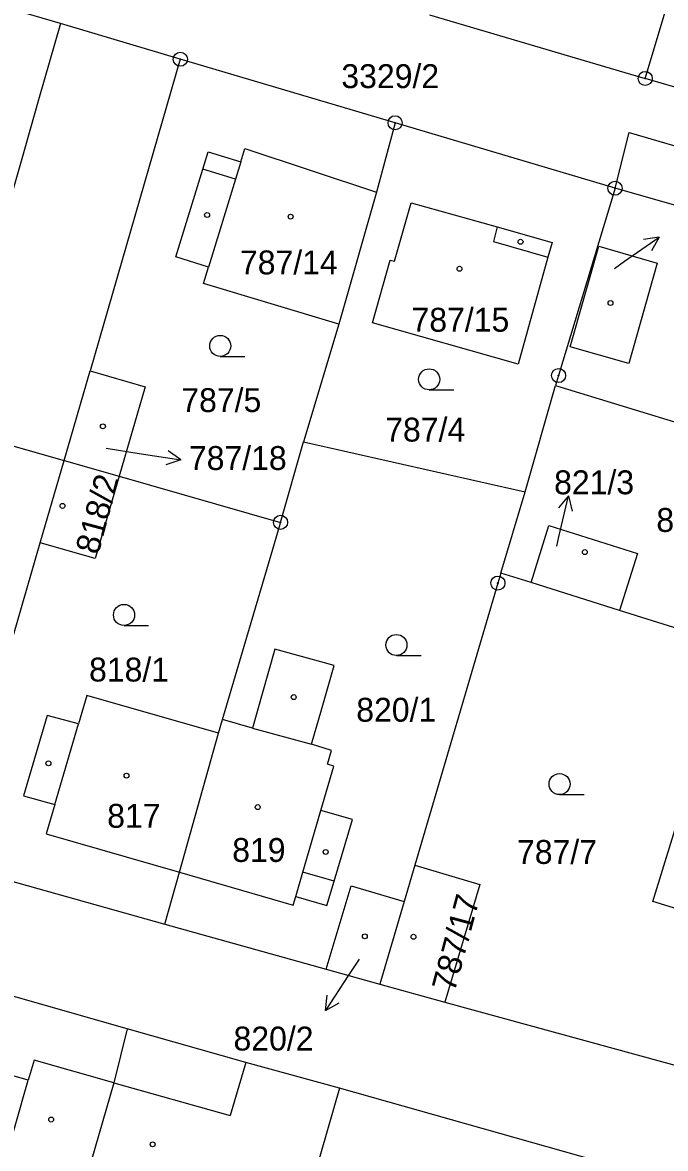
# Model space of a CAD drawing. Extents: x -733394 to -722299, y -1082822 to -1075049.
# Drawn here: x -727949 to -727903.3, y -1079541.3 to -1079461.1 of the extents above; entities that cross this region are included whole.
import ezdxf

# ---------------------------------------------------------------- set-up
doc = ezdxf.new("R2010")
doc.units = 0
for name, color, linetype in [('Hranice parcel', 7, 'Continuous'), ('Parcelní čísla', 7, 'Continuous'), ('Pop  PČ popisy', 7, 'Continuous'), ('Vnitřní kresba', 7, 'Continuous'), ('Značky bodu BP', 7, 'Continuous'), ('Značky budov', 7, 'Continuous'), ('Značky kultur', 7, 'Continuous')]:
    doc.layers.add(name, color=color, linetype=linetype)

msp = doc.modelspace()

# ---------------------------------------------------------------- linework, layer by layer
at = {"layer": 'Hranice parcel'}
for p, q in [((-727904.76, -1079465.11), (-727900.16, -1079449.75)), ((-727946.35, -1079461.21), (-727963.12, -1079456.31)), ((-727920.1, -1079460.58), (-727904.76, -1079465.11)), ((-727937.82, -1079463.75), (-727946.35, -1079461.21)), ((-727937.82, -1079463.75), (-727944.24, -1079485.92)), ((-727922.55, -1079468.27), (-727937.82, -1079463.75)), ((-727900.39, -1079466.39), (-727904.76, -1079465.11)), ((-727922.55, -1079468.27), (-727923.86, -1079473.2)), ((-727906.91, -1079472.93), (-727922.55, -1079468.27)), ((-727923.86, -1079473.2), (-727926.55, -1079482.61)), ((-727926.55, -1079482.61), (-727929.05, -1079490.99)), ((-727946.09, -1079492.3), (-727944.24, -1079485.92)), ((-727913.31, -1079494.53), (-727911.13, -1079486.97)), ((-727911.13, -1079486.97), (-727894.02, -1079492.21)), ((-727961.46, -1079487.91), (-727946.09, -1079492.3)), ((-727930.69, -1079496.71), (-727929.05, -1079490.99)), ((-727929.05, -1079490.99), (-727913.31, -1079494.53)), ((-727947.78, -1079498.16), (-727946.09, -1079492.3)), ((-727946.09, -1079492.3), (-727942.18, -1079493.42)), ((-727942.18, -1079493.42), (-727930.69, -1079496.71)), ((-727915.03, -1079500.32), (-727913.31, -1079494.53)), ((-727950.3, -1079506.88), (-727947.78, -1079498.16)), ((-727912.88, -1079501), (-727915.03, -1079500.32)), ((-727906.58, -1079502.98), (-727912.88, -1079501)), ((-727884.67, -1079509.87), (-727906.58, -1079502.98)), ((-727935.1, -1079511.72), (-727934.82, -1079510.75)), ((-727937.89, -1079521.62), (-727935.1, -1079511.72)), ((-727954.37, -1079520.98), (-727938.93, -1079525.32)), ((-727921.14, -1079521.12), (-727921.91, -1079523.69)), ((-727938.93, -1079525.32), (-727937.89, -1079521.62)), ((-727921.91, -1079523.69), (-727923.63, -1079529.59)), ((-727938.93, -1079525.32), (-727927.45, -1079528.52)), ((-727941.59, -1079532.77), (-727956.81, -1079528.43)), ((-727927.45, -1079528.52), (-727923.63, -1079529.59)), ((-727923.63, -1079529.59), (-727919, -1079530.86)), ((-727941.59, -1079532.77), (-727942.56, -1079536.6)), ((-727942.56, -1079536.6), (-727945.32, -1079546.14)), ((-727926.5, -1079536.99), (-727928.68, -1079544.56)), ((-727895.83, -1079545.64), (-727926.5, -1079536.99))]:
    msp.add_line(p, q, dxfattribs=at)
for points in [[(-727946.35, -1079461.21), (-727947.9, -1079466.63), (-727949.1, -1079470.83), (-727950.81, -1079476.82), (-727951.24, -1079478.31), (-727968.06, -1079473.53), (-727963.12, -1079456.31)], [(-727906.91, -1079472.93), (-727905.91, -1079468.96), (-727874.74, -1079478.07)], [(-727926.55, -1079482.61), (-727936.17, -1079479.7), (-727935.81, -1079478.54), (-727938.15, -1079477.82), (-727936.23, -1079471.57), (-727935.85, -1079470.33), (-727933.51, -1079471.04), (-727933.24, -1079470.11), (-727923.86, -1079473.2)], [(-727906.91, -1079472.93), (-727910.92, -1079486.26), (-727911.13, -1079486.97)], [(-727876.2, -1079482.76), (-727877.72, -1079481.28), (-727879.94, -1079480.64), (-727906.91, -1079472.93)], [(-727911.38, -1079476.8), (-727911.68, -1079477.84), (-727913.8, -1079485.44), (-727924.16, -1079482.52), (-727922.9, -1079478.05), (-727922.59, -1079478.13), (-727921.4, -1079473.97), (-727915.28, -1079475.67), (-727911.38, -1079476.8)], [(-727905.93, -1079485.41), (-727910.1, -1079484.21), (-727908.05, -1079477.06), (-727903.91, -1079478.25), (-727905.93, -1079485.41)], [(-727944.24, -1079485.92), (-727940.31, -1079487.06), (-727942.18, -1079493.42)], [(-727942.18, -1079493.42), (-727943.87, -1079499.29), (-727947.78, -1079498.16)], [(-727934.82, -1079510.75), (-727931.37, -1079499.02), (-727930.73, -1079496.84), (-727930.69, -1079496.71)], [(-727912.88, -1079501), (-727911.61, -1079496.94), (-727905.3, -1079498.92), (-727906.58, -1079502.98)], [(-727915.03, -1079500.32), (-727915.24, -1079501.03), (-727921.14, -1079521.12)], [(-727937.89, -1079521.62), (-727929.79, -1079523.96), (-727929.61, -1079523.33), (-727927.39, -1079523.99), (-727926.87, -1079522.25), (-727925.57, -1079517.87), (-727927.83, -1079517.21), (-727926.91, -1079514.06), (-727927.36, -1079513.92), (-727927.08, -1079512.95), (-727928.5, -1079512.51), (-727927.79, -1079510.06), (-727926.88, -1079506.9), (-727931.09, -1079505.74), (-727931.99, -1079508.91), (-727932.69, -1079511.37), (-727934.82, -1079510.75)], [(-727935.1, -1079511.72), (-727944.46, -1079509.04), (-727945.06, -1079511.06), (-727947.28, -1079510.45), (-727948.98, -1079516.17), (-727946.74, -1079516.79), (-727947.36, -1079518.88), (-727937.89, -1079521.62)], [(-727904.21, -1079523.69), (-727901.38, -1079514.47), (-727900.81, -1079512.57), (-727895.1, -1079514.33), (-727892.92, -1079515), (-727893.51, -1079516.91), (-727891.52, -1079517.53), (-727894.41, -1079526.71), (-727904.21, -1079523.69)], [(-727921.14, -1079521.12), (-727916.52, -1079522.48), (-727919, -1079530.86)], [(-727927.45, -1079528.52), (-727925.67, -1079522.58), (-727921.91, -1079523.69)], [(-727919, -1079530.86), (-727895.39, -1079537.34), (-727892.65, -1079535.88)], [(-727926.5, -1079536.99), (-727933.17, -1079535.15), (-727941.59, -1079532.77)], [(-727942.56, -1079536.6), (-727948.22, -1079535), (-727948.63, -1079536.42), (-727950.37, -1079535.91), (-727952.63, -1079543.73), (-727950.88, -1079544.23), (-727950.98, -1079544.57), (-727951.65, -1079547.6), (-727953.95, -1079558), (-727954.57, -1079560.17)]]:
    msp.add_lwpolyline(points, dxfattribs=at)
at = {"layer": 'Pop  PČ popisy'}
for p, q in [((-727906.23, -1079478.13), (-727903.772, -1079476.409)), ((-727903.772, -1079476.409), (-727904.879, -1079476.573)), ((-727903.772, -1079476.409), (-727904.305, -1079477.393)), ((-727906.94, -1079478.63), (-727906.23, -1079478.13)), ((-727943.09, -1079491.44), (-727940.74, -1079491.8)), ((-727940.74, -1079491.8), (-727937.776, -1079492.269)), ((-727937.776, -1079492.269), (-727938.843, -1079492.607)), ((-727937.776, -1079492.269), (-727938.687, -1079491.618)), ((-727910.225, -1079494.816), (-727910.938, -1079495.679)), ((-727910.9, -1079497.74), (-727910.225, -1079494.816)), ((-727910.225, -1079494.816), (-727909.962, -1079495.904)), ((-727911.05, -1079498.41), (-727910.9, -1079497.74)), ((-727925.1, -1079527.79), (-727925.86, -1079528.95)), ((-727925.86, -1079528.95), (-727927.494, -1079531.467)), ((-727927.494, -1079531.467), (-727927.369, -1079530.354)), ((-727927.494, -1079531.467), (-727926.529, -1079530.9))]:
    msp.add_line(p, q, dxfattribs=at)
at = {"layer": 'Vnitřní kresba'}
for p, q in [((-727933.51, -1079471.04), (-727933.89, -1079472.29)), ((-727933.89, -1079472.29), (-727936.23, -1079471.57)), ((-727933.89, -1079472.29), (-727935.81, -1079478.54)), ((-727915.28, -1079475.67), (-727915.55, -1079476.73)), ((-727915.55, -1079476.73), (-727911.68, -1079477.84)), ((-727946.74, -1079516.79), (-727945.06, -1079511.06)), ((-727932.69, -1079511.37), (-727928.5, -1079512.51)), ((-727929.1, -1079521.6), (-727927.83, -1079517.21)), ((-727929.61, -1079523.33), (-727929.1, -1079521.6)), ((-727926.87, -1079522.25), (-727929.1, -1079521.6)), ((-727933.17, -1079535.15), (-727934.27, -1079538.93)), ((-727950.88, -1079544.23), (-727948.63, -1079536.42)), ((-727942.56, -1079536.6), (-727934.27, -1079538.93))]:
    msp.add_line(p, q, dxfattribs=at)
at = {"layer": 'Značky bodu BP'}
for centre, radius in [((-727937.82, -1079463.75), 0.5), ((-727937.82, -1079463.75), 0.0303), ((-727904.76, -1079465.11), 0.5), ((-727904.76, -1079465.11), 0.0303), ((-727922.55, -1079468.27), 0.5), ((-727922.55, -1079468.27), 0.0303), ((-727906.91, -1079472.93), 0.5), ((-727906.91, -1079472.93), 0.0303), ((-727910.92, -1079486.26), 0.5), ((-727910.92, -1079486.26), 0.0303), ((-727930.69, -1079496.71), 0.5), ((-727930.69, -1079496.71), 0.0303), ((-727915.24, -1079501.03), 0.5), ((-727915.24, -1079501.03), 0.0303)]:
    msp.add_circle(centre, radius, dxfattribs=at)
at = {"layer": 'Značky budov'}
for centre in [(-727935.917, -1079474.829), (-727929.977, -1079474.949), (-727913.627, -1079476.739), (-727917.967, -1079478.659), (-727907.227, -1079481.099), (-727943.327, -1079489.879), (-727946.197, -1079495.539), (-727909.057, -1079498.829), (-727929.757, -1079509.149), (-727947.197, -1079513.859), (-727941.647, -1079514.739), (-727932.317, -1079516.979), (-727927.487, -1079520.169), (-727924.697, -1079526.179), (-727921.237, -1079526.209), (-727947.007, -1079539.219), (-727939.787, -1079540.979)]:
    msp.add_circle(centre, 0.175, dxfattribs=at)
at = {"layer": 'Značky kultur'}
for p, q in [((-727934.983, -1079484.9), (-727933.233, -1079484.9)), ((-727920.123, -1079487.28), (-727918.373, -1079487.28)), ((-727941.823, -1079504.05), (-727940.073, -1079504.05)), ((-727922.453, -1079506.19), (-727920.703, -1079506.19)), ((-727910.853, -1079516.09), (-727909.103, -1079516.09))]:
    msp.add_line(p, q, dxfattribs=at)
for centre in [(-727934.983, -1079484.15), (-727920.123, -1079486.53), (-727941.823, -1079503.3), (-727922.453, -1079505.44), (-727910.853, -1079515.34)]:
    msp.add_circle(centre, 0.75, dxfattribs=at)

# ---------------------------------------------------------------- texts
at = {"layer": 'Parcelní čísla'}
for s, p in [('3329/2', (-727926.37, -1079465.8)), ('787/14', (-727933.58, -1079479.06)), ('787/15', (-727921.38, -1079483.14)), ('787/5', (-727937.75, -1079488.86)), ('787/4', (-727923.25, -1079490.96)), ('787/18', (-727937.21, -1079492.983)), ('821/3', (-727911.24, -1079494.71)), ('821/1', (-727903.97, -1079497.39)), ('818/1', (-727944.31, -1079508.04)), ('820/1', (-727925.31, -1079510.9)), ('817', (-727943.02, -1079518.45)), ('819', (-727934.13, -1079520.88)), ('787/7', (-727913.88, -1079521.02)), ('820/2', (-727934.036, -1079534.303))]:
    msp.add_text(s, height=1.7, dxfattribs=at).set_placement(p)
for s, p in [('818/2', (-727943.658, -1079499.069)), ('787/17', (-727918.318, -1079530.209))]:
    msp.add_text(s, height=1.7, rotation=75, dxfattribs=at).set_placement(p)

doc.saveas('drawing.dxf')
